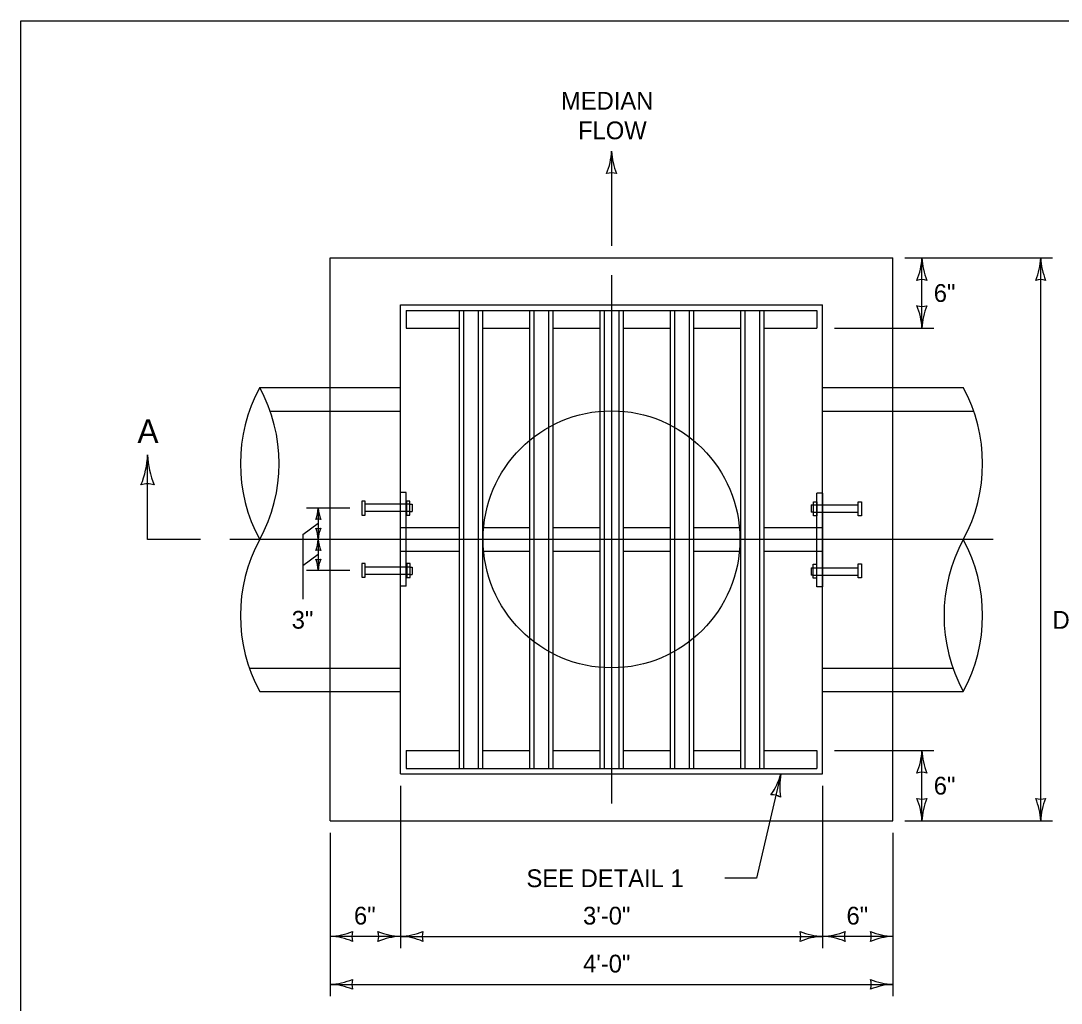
# Model space of a CAD drawing. Extents: x 49991.4 to 50021, y 49987.6 to 50011.4.
# Drawn here: x 49999.384 to 50002.895, y 49995.684 to 49998.999 of the extents above; entities that cross this region are included whole.
import ezdxf

# ---------------------------------------------------------------- set-up
doc = ezdxf.new("R2010")
doc.units = 0
for name, color, linetype in [('Level 1', 7, 'Continuous'), ('Level 2', 7, 'Continuous'), ('Level 3', 7, 'Continuous'), ('Level 4', 7, 'Continuous'), ('Level 5', 7, 'Continuous'), ('Level 6', 7, 'Continuous')]:
    doc.layers.add(name, color=color, linetype=linetype)

msp = doc.modelspace()

# ---------------------------------------------------------------- linework, layer by layer
at = {"layer": 'Level 1'}
for p, q in [((50000.4274, 49998.1994), (50002.3274, 49998.1994)), ((50000.4274, 49997.3764), (50000.4274, 49998.1994)), ((50000.4274, 49998.1994), (50002.3274, 49998.1994)), ((50002.3274, 49996.2993), (50002.3274, 49998.1994)), ((50000.6649, 49996.4576), (50000.6649, 49998.041)), ((50000.6649, 49998.041), (50002.0899, 49998.041)), ((50000.6839, 49998.022), (50002.0709, 49998.022)), ((50000.6839, 49998.022), (50000.6839, 49997.9619)), ((50000.8628, 49998.022), (50000.8628, 49997.21)), ((50000.942, 49998.022), (50000.942, 49996.4766)), ((50001.1003, 49998.022), (50001.1003, 49996.4766)), ((50001.1795, 49998.022), (50001.1795, 49996.4766)), ((50001.3378, 49998.022), (50001.3378, 49996.4766)), ((50001.417, 49998.022), (50001.417, 49996.4766)), ((50001.5753, 49998.022), (50001.5753, 49997.2049)), ((50001.6545, 49998.022), (50001.6545, 49996.4766)), ((50001.8128, 49998.022), (50001.8128, 49996.4766)), ((50001.892, 49998.022), (50001.892, 49996.4766)), ((50002.0709, 49998.022), (50002.0709, 49997.9619)), ((50002.0899, 49996.4576), (50002.0899, 49998.041)), ((50000.6839, 49997.9619), (50000.8628, 49997.9619)), ((50000.942, 49997.9619), (50001.1003, 49997.9619)), ((50001.1795, 49997.9619), (50001.3378, 49997.9619)), ((50001.417, 49997.9619), (50001.5753, 49997.9619)), ((50001.6545, 49997.9619), (50001.8128, 49997.9619)), ((50001.892, 49997.9619), (50002.0709, 49997.9619)), ((50002.3274, 49997.7614), (50002.5649, 49997.7614)), ((50000.6649, 49997.2494), (50000.6649, 49997.4077)), ((50000.6848, 49997.4077), (50000.6649, 49997.4077)), ((50000.6848, 49997.2494), (50000.6848, 49997.4077)), ((50002.0709, 49997.2472), (50002.0709, 49997.4055)), ((50002.0907, 49997.4055), (50002.0709, 49997.4055)), ((50002.0907, 49997.2472), (50002.0907, 49997.4055)), ((50000.4274, 49997.0801), (50000.4274, 49997.3764)), ((50000.6968, 49997.3681), (50000.7045, 49997.3681)), ((50000.7045, 49997.3681), (50000.7045, 49997.3434)), ((50002.0511, 49997.3659), (50002.0511, 49997.3412)), ((50002.0511, 49997.3659), (50002.0589, 49997.3659)), ((50000.6968, 49997.3434), (50000.7045, 49997.3434)), ((50002.0589, 49997.3412), (50002.0511, 49997.3412)), ((50000.6649, 49997.2889), (50000.8628, 49997.2889)), ((50000.942, 49997.2889), (50001.1003, 49997.2889)), ((50001.1798, 49997.2889), (50001.3378, 49997.2889)), ((50001.417, 49997.2889), (50001.5753, 49997.2889)), ((50001.6545, 49997.2889), (50001.8128, 49997.2889)), ((50001.892, 49997.2889), (50002.0899, 49997.2889)), ((50000.6649, 49997.091), (50000.6649, 49997.2494)), ((50000.6848, 49997.091), (50000.6848, 49997.2494)), ((50002.0709, 49997.0889), (50002.0709, 49997.2472)), ((50002.0907, 49997.0889), (50002.0907, 49997.2472)), ((50000.6649, 49997.2098), (50000.8628, 49997.2098)), ((50000.8628, 49997.2098), (50000.8628, 49996.4766)), ((50000.942, 49997.2098), (50001.1003, 49997.2098)), ((50001.1795, 49997.2098), (50001.3378, 49997.2098)), ((50001.417, 49997.2098), (50001.5753, 49997.2098)), ((50001.5753, 49997.2098), (50001.5753, 49996.4766)), ((50001.6545, 49997.2098), (50001.8128, 49997.2098)), ((50001.892, 49997.2098), (50002.0899, 49997.2098)), ((50000.6973, 49997.1554), (50000.7045, 49997.1554)), ((50000.7045, 49997.1554), (50000.7045, 49997.1306)), ((50002.0511, 49997.1532), (50002.0511, 49997.1284)), ((50002.0511, 49997.1532), (50002.0583, 49997.1532)), ((50000.6973, 49997.1306), (50000.7045, 49997.1306)), ((50002.0583, 49997.1284), (50002.0511, 49997.1284)), ((50000.4274, 49996.2993), (50000.4274, 49997.0801)), ((50000.6848, 49997.091), (50000.6649, 49997.091)), ((50002.0907, 49997.0889), (50002.0709, 49997.0889)), ((50002.3274, 49996.7359), (50002.5649, 49996.7359)), ((50000.6839, 49996.5368), (50000.8628, 49996.5368)), ((50000.6839, 49996.5368), (50000.6839, 49996.4766)), ((50000.942, 49996.5368), (50001.1003, 49996.5368)), ((50001.1795, 49996.5368), (50001.3378, 49996.5368)), ((50001.417, 49996.5368), (50001.5753, 49996.5368)), ((50001.6545, 49996.5368), (50001.8128, 49996.5368)), ((50001.892, 49996.5368), (50002.0709, 49996.5368)), ((50002.0709, 49996.5368), (50002.0709, 49996.4766)), ((50000.6839, 49996.4766), (50002.0709, 49996.4766)), ((50000.6649, 49996.4576), (50002.0899, 49996.4576)), ((50000.4274, 49996.2993), (50002.3274, 49996.2993))]:
    msp.add_line(p, q, dxfattribs=at)
for points in [[(49999.3835, 49998.9992), (50016.7501, 49998.9992), (50016.7501, 49987.7988), (49999.3835, 49987.7988)], [(50000.6855, 49997.3779), (50000.6855, 49997.3309), (50000.6968, 49997.3309), (50000.6968, 49997.3779)], [(50002.07, 49997.3757), (50002.07, 49997.3286), (50002.0589, 49997.3286), (50002.0589, 49997.3757)], [(50000.6861, 49997.1679), (50000.6861, 49997.1207), (50000.6973, 49997.1207), (50000.6973, 49997.1679)], [(50002.0695, 49997.1656), (50002.0695, 49997.1186), (50002.0583, 49997.1186), (50002.0583, 49997.1656)]]:
    msp.add_lwpolyline(points, close=True, dxfattribs=at)
for centre, start_param, end_param in [((50002.0934, 49997.505), 1.072803, 2.06879), ((50003.0364, 49996.9923), 4.214396, 5.210382), ((50002.0934, 49996.9923), 1.072803, 2.06879)]:
    msp.add_ellipse(centre, major_axis=(0, -0.5367), ratio=0.99996, start_param=start_param, end_param=end_param, dxfattribs=at)
at = {"layer": 'Level 3'}
for p, q in [((50001.3774, 49998.5595), (50001.3774, 49998.2394)), ((50002.3674, 49998.1994), (50002.866, 49998.1994)), ((50002.4251, 49997.9619), (50002.4251, 49998.1994)), ((50002.826, 49996.2993), (50002.826, 49998.1994)), ((50002.1299, 49997.9619), (50002.4651, 49997.9619)), ((50000.4946, 49997.3544), (50000.3474, 49997.3544)), ((50000.3874, 49997.3544), (50000.3874, 49997.2494)), ((50000.3359, 49997.2652), (50000.3874, 49997.3039)), ((50000.3359, 49997.2652), (50000.3359, 49997.048)), ((50000.3874, 49997.2494), (50000.3874, 49997.1448)), ((50000.3359, 49997.1611), (50000.3874, 49997.1998)), ((50000.4946, 49997.1448), (50000.3474, 49997.1448)), ((50002.1299, 49996.5368), (50002.4651, 49996.5368)), ((50002.4251, 49996.2993), (50002.4251, 49996.5368)), ((50001.9491, 49996.4576), (50001.8664, 49996.1057)), ((50000.6649, 49996.4176), (50000.6649, 49995.8695)), ((50002.0899, 49996.4176), (50002.0899, 49995.8695)), ((50002.3674, 49996.2993), (50002.866, 49996.2993)), ((50000.4274, 49996.2593), (50000.4274, 49995.7077)), ((50002.3274, 49996.2593), (50002.3274, 49995.7077)), ((50000.4274, 49996.2493), (50000.4274, 49995.881)), ((50001.8664, 49996.1057), (50001.7599, 49996.1057)), ((50000.6649, 49995.9095), (50000.4274, 49995.9095)), ((50000.6649, 49995.9095), (50002.0899, 49995.9095)), ((50002.3274, 49995.9095), (50002.0899, 49995.9095)), ((50000.4274, 49995.7477), (50002.3274, 49995.7477))]:
    msp.add_line(p, q, dxfattribs=at)
for centre, radius, start, end in [((50002.203, 49998.2086), 0.2223, 337.456, 357.6395), ((50002.6578, 49998.2109), 0.233, 182.8273, 202.0772), ((50002.4251, 49998.0712), 0.0548, 72.1388, 107.8612), ((50002.4251, 49998.0901), 0.0548, 252.1388, 287.8612), ((50002.1924, 49997.9504), 0.233, 2.8273, 22.0772), ((50002.6472, 49997.9527), 0.2223, 157.456, 177.6395), ((50000.2763, 49997.359), 0.1112, 337.456, 357.6395), ((50000.5038, 49997.3601), 0.1165, 182.8273, 202.0772), ((50000.3874, 49997.2903), 0.0274, 72.1388, 107.8612), ((50000.3874, 49997.3135), 0.0274, 252.1388, 287.8612), ((50000.271, 49997.2437), 0.1165, 2.8273, 22.0772), ((50000.4985, 49997.2448), 0.1112, 157.456, 177.6395), ((50000.2763, 49997.254), 0.1112, 337.456, 357.6395), ((50000.5038, 49997.2551), 0.1165, 182.8273, 202.0772), ((50000.3874, 49997.1853), 0.0274, 72.1388, 107.8612), ((50000.3874, 49997.2089), 0.0274, 252.1388, 287.8612), ((50000.271, 49997.1391), 0.1165, 2.8273, 22.0772), ((50000.4985, 49997.1402), 0.1112, 157.456, 177.6395), ((50002.203, 49996.546), 0.2223, 337.456, 357.6395), ((50002.6578, 49996.5483), 0.233, 182.8273, 202.0772), ((50002.4251, 49996.4086), 0.0548, 72.1388, 107.8612), ((50002.4251, 49996.4275), 0.0548, 252.1388, 287.8612), ((50002.1924, 49996.2878), 0.233, 2.8273, 22.0772), ((50002.6472, 49996.2901), 0.2223, 157.456, 177.6395), ((50000.6741, 49996.1316), 0.2223, 247.456, 267.6395), ((50000.5367, 49995.9095), 0.0548, 342.1388, 17.8612), ((50000.6764, 49995.6768), 0.233, 92.8273, 112.0772), ((50002.3366, 49996.1316), 0.2223, 247.456, 267.6395), ((50002.1992, 49995.9095), 0.0548, 342.1388, 17.8612), ((50002.3389, 49995.6768), 0.233, 92.8273, 112.0772), ((50000.4159, 49995.9804), 0.233, 272.8273, 292.0772), ((50000.4182, 49995.5256), 0.2223, 67.456, 87.6395), ((50000.5556, 49995.7477), 0.0548, 162.1388, 197.8612), ((50002.3366, 49995.9698), 0.2223, 247.456, 267.6395), ((50002.1992, 49995.7477), 0.0548, 342.1388, 17.8612), ((50002.3389, 49995.515), 0.233, 92.8273, 112.0772)]:
    msp.add_arc(centre, radius, start, end, dxfattribs=at)
for centre, major_axis, start_param, end_param in [((50001.1553, 49998.5687), (0, -0.2223), 1.177329, 1.529598), ((50001.6101, 49998.571), (0, -0.233), 4.761735, 5.097708), ((50001.3774, 49998.4313), (0, 0.0548), 5.971449, 6.594922), ((50002.6039, 49998.2086), (0, -0.2223), 1.177329, 1.529598), ((50003.0587, 49998.2109), (0, -0.233), 4.761735, 5.097708), ((50002.826, 49998.0712), (0, 0.0548), 5.971449, 6.594922), ((49999.5153, 49997.5466), (0, -0.2964), 1.177329, 1.529598), ((50000.1218, 49997.5497), (0, -0.3107), 4.761735, 5.097708), ((49999.8115, 49997.3634), (0, 0.073), 5.971449, 6.594922), ((50001.7348, 49996.5169), (0, -0.2223), 0.946632, 1.2989), ((50001.7349, 49996.5173), (0, -0.2223), 0.946632, 1.2989), ((50002.1781, 49996.4152), (0, 0.233), 1.389444, 1.725418), ((50002.1783, 49996.4156), (0, 0.233), 1.389444, 1.725418), ((50001.9196, 49996.3324), (0, 0.0548), 5.740751, 6.364224), ((50001.9198, 49996.3328), (0, 0.0548), 5.740751, 6.364224), ((50002.826, 49996.4275), (0, -0.0548), 5.971449, 6.594922), ((50002.5933, 49996.2878), (0, 0.233), 4.761735, 5.097708), ((50003.0481, 49996.2901), (0, 0.2223), 1.177329, 1.529598), ((50000.4159, 49996.1422), (0, -0.233), 0.049346, 0.385319), ((50000.4182, 49995.6874), (0, 0.2223), 5.889718, 6.241987), ((50000.5556, 49995.9095), (0, 0.0548), 1.25906, 1.882533), ((50000.6534, 49996.1422), (0, -0.233), 0.049346, 0.385319), ((50000.6557, 49995.6874), (0, 0.2223), 5.889718, 6.241987), ((50000.7931, 49995.9095), (0, 0.0548), 1.25906, 1.882533), ((50002.0991, 49996.1316), (0, -0.2223), 5.889718, 6.241987), ((50001.9617, 49995.9095), (0, -0.0548), 1.25906, 1.882533), ((50002.1014, 49995.6768), (0, 0.233), 0.049346, 0.385319), ((50002.0784, 49996.1422), (0, -0.233), 0.049346, 0.385319), ((50002.0807, 49995.6874), (0, 0.2223), 5.889718, 6.241987), ((50002.2181, 49995.9095), (0, 0.0548), 1.25906, 1.882533)]:
    msp.add_ellipse(centre, major_axis=major_axis, ratio=0.99996, start_param=start_param, end_param=end_param, dxfattribs=at)
at = {"layer": 'Level 4'}
for p, q in [((50000.8778, 49998.022), (50000.8778, 49996.4766)), ((50000.9272, 49998.022), (50000.9272, 49996.4766)), ((50001.1152, 49998.022), (50001.1152, 49996.4766)), ((50001.1647, 49998.022), (50001.1647, 49996.4766)), ((50001.3527, 49998.022), (50001.3527, 49996.4766)), ((50001.4022, 49998.022), (50001.4022, 49996.4766)), ((50001.5902, 49998.022), (50001.5902, 49996.4766)), ((50001.6396, 49998.022), (50001.6396, 49996.4766)), ((50001.8277, 49998.022), (50001.8277, 49996.4766)), ((50001.8771, 49998.022), (50001.8771, 49996.4766)), ((50000.19, 49997.7614), (50000.4274, 49997.7614)), ((50000.4274, 49997.7614), (50000.6649, 49997.7614)), ((50002.0899, 49997.7614), (50002.3274, 49997.7614)), ((50000.225, 49997.6823), (50000.6649, 49997.6823)), ((50002.0899, 49997.6823), (50002.6, 49997.6823)), ((50000.6968, 49997.3681), (50000.5462, 49997.3681)), ((50002.0589, 49997.3659), (50002.2095, 49997.3659)), ((50000.6968, 49997.3434), (50000.5462, 49997.3434)), ((50002.0589, 49997.3412), (50002.2095, 49997.3412)), ((50000.6973, 49997.1554), (50000.5462, 49997.1554)), ((50002.0583, 49997.1532), (50002.2095, 49997.1532)), ((50000.6973, 49997.1306), (50000.5462, 49997.1306)), ((50002.0583, 49997.1284), (50002.2095, 49997.1284)), ((50000.1549, 49996.815), (50000.6649, 49996.815)), ((50002.0899, 49996.815), (50002.5299, 49996.815)), ((50000.19, 49996.7359), (50000.4274, 49996.7359)), ((50000.4274, 49996.7359), (50000.6649, 49996.7359)), ((50002.0899, 49996.7359), (50002.3274, 49996.7359))]:
    msp.add_line(p, q, dxfattribs=at)
for points in [[(50000.5346, 49997.3779), (50000.5346, 49997.3309), (50000.5458, 49997.3309), (50000.5458, 49997.3779)], [(50002.2211, 49997.3757), (50002.2211, 49997.3286), (50002.2099, 49997.3286), (50002.2099, 49997.3757)], [(50000.5346, 49997.1683), (50000.5346, 49997.1213), (50000.5458, 49997.1213), (50000.5458, 49997.1683)], [(50002.2211, 49997.1662), (50002.2211, 49997.119), (50002.2099, 49997.119), (50002.2099, 49997.1662)]]:
    msp.add_lwpolyline(points, close=True, dxfattribs=at)
for centre, start_param, end_param in [((50000.6615, 49997.505), 4.214396, 5.210382), ((49999.7185, 49997.505), 1.072803, 2.06879), ((50000.6615, 49996.9923), 4.214396, 5.210382)]:
    msp.add_ellipse(centre, major_axis=(0, -0.5367), ratio=0.99996, start_param=start_param, end_param=end_param, dxfattribs=at)
msp.add_ellipse((50001.3774, 49997.2494), major_axis=(0, 0.4336), ratio=0.99996, dxfattribs=at)
at = {"layer": 'Level 5'}
for p, q in [((50001.3774, 49998.141), (50001.3774, 49996.3576)), ((50002.6653, 49997.2494), (50000.0896, 49997.2494))]:
    msp.add_line(p, q, dxfattribs=at)
at = {"layer": 'Level 6'}
for p, q in [((49999.8115, 49997.2494), (49999.8115, 49997.5344)), ((49999.9896, 49997.2494), (49999.8115, 49997.2494))]:
    msp.add_line(p, q, dxfattribs=at)

# ---------------------------------------------------------------- texts
at = {"layer": 'Level 2'}
for s, height, p in [('MEDIAN', 0.06, (50001.2067, 49998.6995)), ('FLOW', 0.06, (50001.2643, 49998.5995)), ('6"', 0.06, (50002.4651, 49998.0506)), ('A', 0.08, (49999.7771, 49997.5744)), ('3"', 0.06, (50000.2979, 49996.948)), ('D + 2\'-0"', 0.06, (50002.866, 49996.9475)), ('6"', 0.06, (50002.4651, 49996.3881)), ('SEE DETAIL 1', 0.059999, (50001.0903, 49996.0757)), ('6"', 0.06, (50000.5081, 49995.9495)), ('3\'-0"', 0.06, (50001.2813, 49995.9495)), ('6"', 0.06, (50002.1706, 49995.9495)), ('4\'-0"', 0.06, (50001.2813, 49995.7877))]:
    msp.add_text(s, height=height, dxfattribs=at).set_placement(p)

doc.saveas('drawing.dxf')
